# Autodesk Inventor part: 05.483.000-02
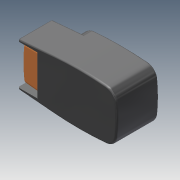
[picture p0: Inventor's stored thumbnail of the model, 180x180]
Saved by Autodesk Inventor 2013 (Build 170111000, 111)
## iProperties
Created: 2005-07
Part Number: 05.483.000-02
Material: Steel, Mild
Document SubType Name: Modeling
Designer: tedescj
Manufacturer: Standard
Standards Organization: Custom
Density: 7.86 g/cm^3
Author: PVitaliy
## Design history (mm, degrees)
derived "05.483.000-01.ipt"
feature "Solid1::05.483.000-01.ipt" dims "d0" = 10
tag "TaggingFeature1"
body "Solid1"
